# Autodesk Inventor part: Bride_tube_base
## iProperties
Shininess: 64.0
Length Units: 11269
Angle Units: 11279
Time Units: 11290
Mass Units: 11283
Length Display Precision: 3
Angle Display Precision: 2
Compacted: True
Part Number: Bride_tube_base
Document SubType Name: Modeling
Created: 2008-02
Material: Acier inoxydable, austénitique
Designer: Pascal
Density: 8.03 g/cm^3
Density: 0.0
Volumn: 0.0
Area: 0.0
PropertySet Name: Model Information
Control State: 0
Master: False
Checked Out: False
DESIGNATION: Bride tube corps
Author: Pascal
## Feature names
1. Extrusion1
2. Extrusion2
3. Réseau circulaire1 [Circular Pattern]
4. Extrusion3
